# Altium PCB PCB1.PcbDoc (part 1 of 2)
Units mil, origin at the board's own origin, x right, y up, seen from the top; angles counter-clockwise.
Board outline 6184.85 x 2780 mil, 2 copper layers (Top Layer, Bottom Layer); 130 components, 145 nets, 531 pads, 99 vias.
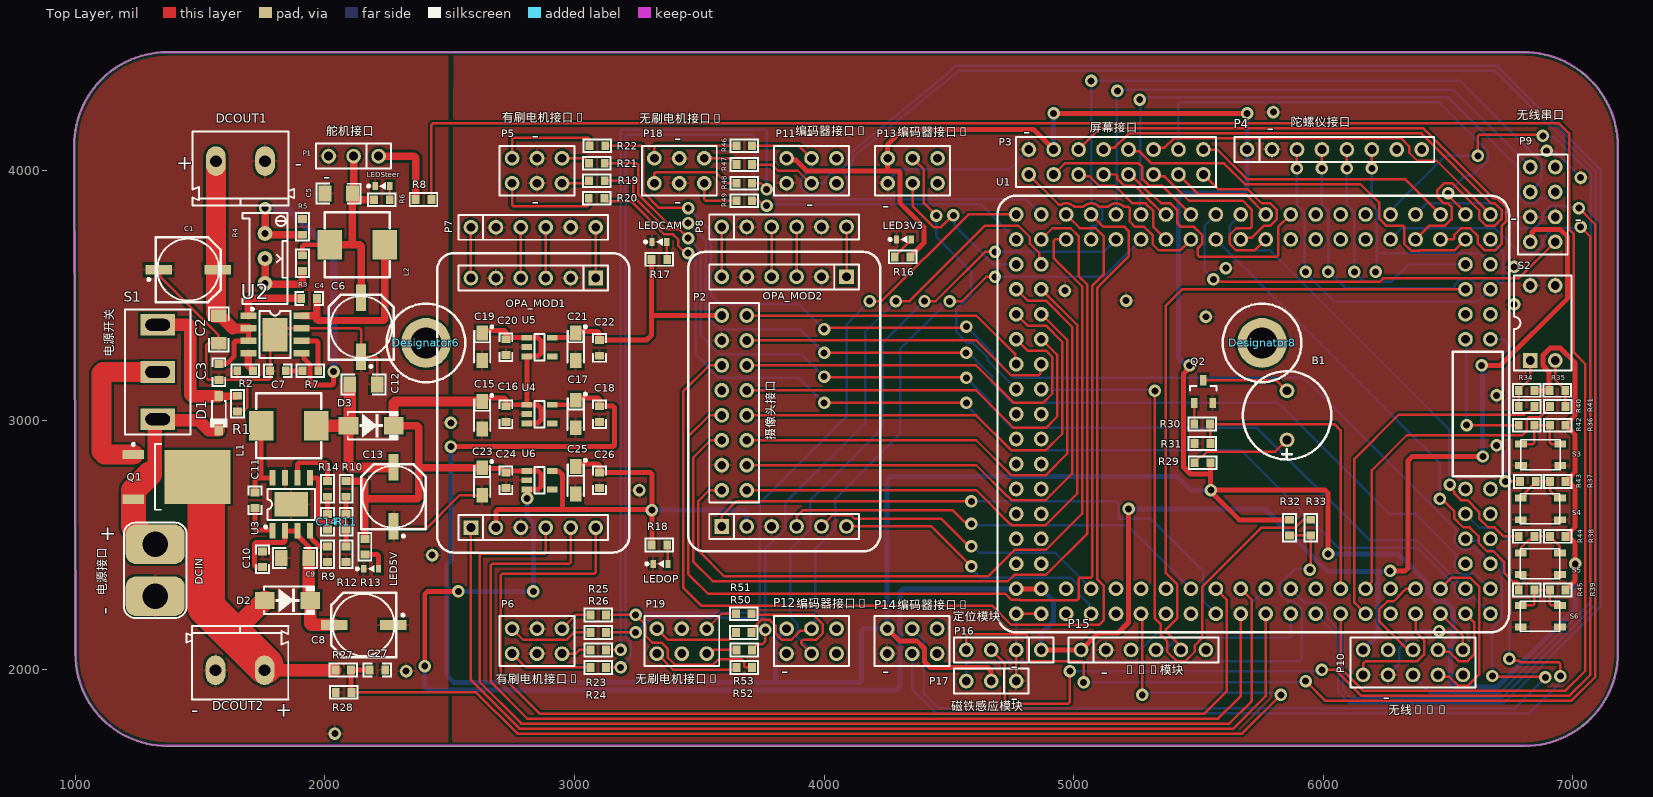
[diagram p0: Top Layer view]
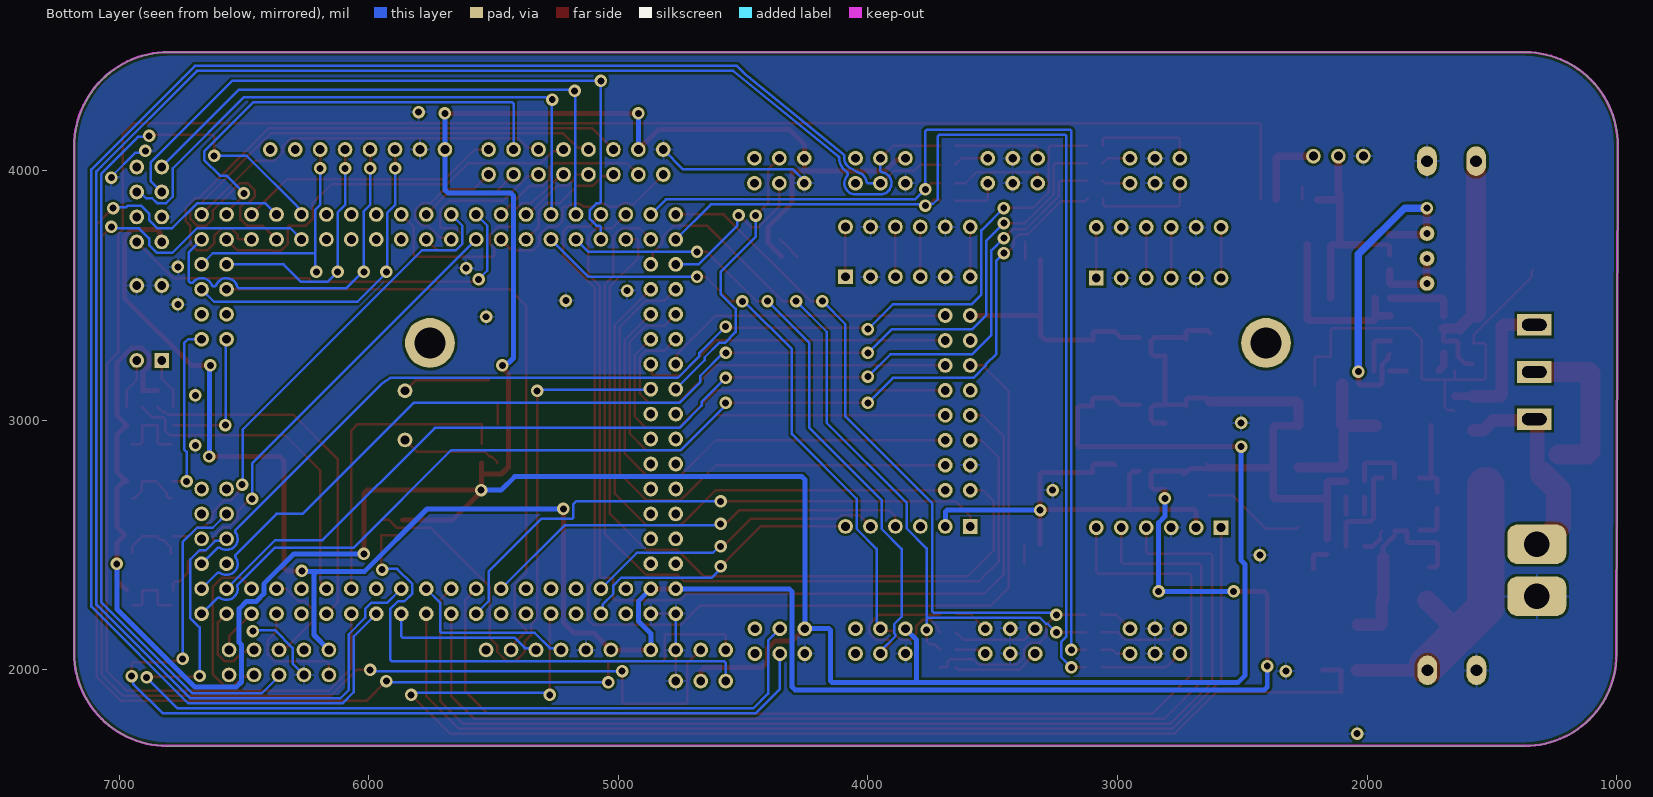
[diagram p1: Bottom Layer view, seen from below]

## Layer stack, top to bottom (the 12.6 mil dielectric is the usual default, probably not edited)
Top Solder: solder mask 0.4, Solder Resist, Dk 3.5
Top Layer: signal copper 1.4
Dielectric 1: dielectric 12.6, FR-4, Dk 4.8
Bottom Layer: signal copper 1.4
Bottom Solder: solder mask 0.4, Solder Resist, Dk 3.5

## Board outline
1000,2062.29 995.15,4100.04 cw(c1367.5,4102.54) 1364.99,4474.88 6802.71,4475 cw(c6802.71,4097.71) 7180,4097.71 7180,2067.32 cw(c6807.68,2067.32) 6807.68,1695 6810,1695 1370,1695 1367.29,1695 cw(c1367.29,2062.29)

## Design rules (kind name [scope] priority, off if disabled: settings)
Clearance [All] p1: gap=10 ignorepadtopadclearanceinfootprint=FALSE except(0: Arc-Hole Track-Hole SMDPad-Hole THPad-Hole Via-Hole Fill-Hole Poly-Hole Region-Hole Text-Hole)
PolygonConnect [All] p1: connectstyle=Relief reliefconductorwidth=10 reliefentries=4 polygonreliefangle="90 Angle" airgapwidth=10
RoutingVias [All] p1: holewidth=28 width=50 viastyle="Through Hole" minholewidth=28 minwidth=50 maxholewidth=28 maxwidth=50
SolderMaskExpansion [All] p1: expansion=4 istentingtop=FALSE
Width [InNetClass('New Class')] p1: maxlimit=20 minlimit=20 preferedwidth=20 minimp=50.000000 maximp=50.000000 favimp=50.000000
30 further rules are at their usual default settings.

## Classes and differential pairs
polygon class PolygonClass_1: GND_L01_P000

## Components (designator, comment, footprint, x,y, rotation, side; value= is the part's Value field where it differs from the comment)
B1 "BEEP" "BEEP 9x5.5mm" 5855,3020 r90 top
C1 "100uF 35V 铝电解" "CAP-E-S 6.3" 1451.89,3603.5 r180 top value=100uF
C2 "4.7uF 35V X5R" CAPC3216[1206]S 1575,3363.62 r90 top value=4.7uF
C3 "100nF 50V X7R" CAPC1608[0603]S-N 1575,3193.5 r90 top value=100nF
C4 "100nF 50V X7R" CAPC1608[0603]S-N 1936.5,3488.5 r0 top value=100nF
C5 "47uF 25V X5R" CAPC3216[1206]S 2054.88,3908.5 r180 top value=47uF
C6 "220uF 25V 铝电解" "CAP-E-S 6.3" 2145,3373.5 r270 top value=220uF
C7 "4.7nF 50V X7R" CAPC1608[0603]S-N 1811.5,3198.5 r0 top value=4.7nF
C8 "100uF 35V 铝电解" "CAP-E-S 6.3" 2155,2180 r0 top value=100uF
C9 "4.7uF 35V X5R" CAPC3216[1206]S 1880.12,2448.5 r0 top value=4.7uF
C10 "100nF 50V X7R" CAPC1608[0603]S-N 1750,2443.5 r90 top value=100nF
C11 "100nF 50V X7R" CAPC1608[0603]S-N 1720,2680 r90 top value=100nF
C12 "47uF 25V X5R" CAPC3216[1206]S 2155,3143.5 r180 top value=47uF
C13 "220uF 25V 铝电解" "CAP-E-S 6.3" 2275,2693.5 r270 top value=220uF
C14 "4.7nF 50V X7R" CAPC1608[0603]S-N 2010,2593.5 r90 top value=4.7nF
C15 "10uF 16V 钽电容" "CAP-T-S 3216" 2630,3020 r270 top value=10uF
C16 "100nF 50V X7R" CAPC1608[0603]S-N 2725,3025 r90 top value=100nF
C17 "10uF 16V 钽电容" "CAP-T-S 3216" 3005,3025 r270 top value=10uF
C18 "100nF 50V X7R" CAPC1608[0603]S-N 3100,3025 r90 top value=100nF
C19 "10uF 16V 钽电容" "CAP-T-S 3216" 2630,3294.88 r270 top value=10uF
C20 "100nF 50V X7R" CAPC1608[0603]S-N 2725,3293.5 r90 top value=100nF
C21 "10uF 16V 钽电容" "CAP-T-S 3216" 3005,3295 r270 top value=10uF
C22 "100nF 50V X7R" CAPC1608[0603]S-N 3100,3290 r90 top value=100nF
C23 "10uF 16V 钽电容" "CAP-T-S 3216" 2630,2755 r270 top value=10uF
C24 "100nF 50V X7R" CAPC1608[0603]S-N 2725,2760 r90 top value=100nF
C25 "10uF 16V 钽电容" "CAP-T-S 3216" 3005,2760 r270 top value=10uF
C26 "100nF 50V X7R" CAPC1608[0603]S-N 3100,2760 r90 top value=100nF
C27 "100nF 50V X7R" CAPC1608[0603]S-N 2210,2000 r0 top value=100nF
D1 "BZT52C16" SOD-123-L 1575,3028.5 r270 top
D2 "SS54" SMA-L[DO-214AC] 1850,2278.5 r0 top
D3 "SS54" SMA-L[DO-214AC] 2185,2978.5 r0 top
DCIN "T型插头" "Wired T-Header ThroughHole" 1320,2399.17 r0 top
DCOUT1 "KF/WJ/DG 30x connecter" "KF/WJ/DG 301-2p-5.0mm" 1661.57,4038.5 r180 top
DCOUT2 "KF/WJ/DG 30x connecter" "KF/WJ/DG 301-2p-5.0mm" 1660,1998.5 r0 top
Designator6 "Comment" M3x4_L 2405,3310 r0 top
Designator8 "Comment" M3x4_L 5755,3310 r0 top
L1 "4.7uH 5A" "0630 TPC 7*7*3" 1855,2978.5 r0 top value=4.7uH
L2 "4.7uH 5A" "0630 TPC 7*7*3" 2130,3703.5 r180 top value=4.7uH
LED3V3 "翠绿贴片LED" LEDC1608(0603)-L 4320,3725 r0 top
LED5V "翠绿贴片LED" LEDC1608(0603)-L 2185,2405 r0 top
LEDCAM "翠绿贴片LED" LEDC1608(0603)-L 3340,3715 r0 top
LEDOP "翠绿贴片LED" LEDC1608(0603)-L 3345,2425 r0 top
LEDSteer "翠绿贴片LED" LEDC1608(0603)-L 2230.47,3938.5 r0 top
OPA_MOD1 "OPA_MOD" SEEKFREE_4CHANEL_OPAMOD 2835,3070 r0 top
OPA_MOD2 "OPA_MOD" SEEKFREE_4CHANEL_OPAMOD 3840,3075 r0 top
P1 "Header-D-M 1x3P" HDR1X3-M 2215,4058.5 r180 top
P2 "Header-D-F 2x8P" HDR2X8-F 3690,2720 r90 top
P3 "Header-D-F 2x8P" HDR2X8-F 4820,3985 r0 top
P4 "Header-D-M 1x8P" HDR1X8-M 5695,4085 r0 top
P5 "Header-D-M 2x3P" HDR2X3-M 2950,4050 r180 top
P6 "Header-D-M 2x3P" HDR2X3-M 2950,2165 r180 top
P7 "Header-D-M 1x6P" HDR1X6-M 2585,3773.5 r0 top
P8 "Header-D-M 1x6P" HDR1X6-M 3590,3775 r0 top
P9 "Header-D-F 2x4P" HDR2X4-F 6830,4015 r270 top
P10 "Header-D-F 2x5P" HDR2X5-F 6560,2080 r180 top
P11 "Header-D-M 2x3P" HDR2X3-M 4050,4050 r180 top
P12 "Header-D-M 2x3P" HDR2X3-M 4050,2165 r180 top
P13 "Header-D-M 2x3P" HDR2X3-M 4455,4050 r180 top
P14 "Header-D-M 2x3P" HDR2X3-M 4453.03,2165 r180 top
P15 "Header-D-M 1x6P" HDR1X6-M 5030,2080 r0 top
P16 "Header-D-M 1x4P" HDR1X4-M 4870,2080 r180 top
P17 "Header-D-M 1x3P" HDR1X3-M 4770,1955 r180 top
P18 "Header-D-M 2x3P" HDR2X3-M 3320,3950 r0 top
P19 "Header-D-M 2x3P" HDR2X3-M 3330,2065 r0 top
Q1 "HY19P03" TO-252AA 1361.06,2773.5 r0 top
Q2 "S8050" SOT-23 5520,3115 r90 top
R1 "10K ±1%" RESC1608[0603]S-N 1650,3067.01 r90 top value=10K
R2 "200K ±1%" RESC1608[0603]S-N 1680,3198.5 r0 top value=200K
R3 "27K ±1%" RESC1608[0603]S-N 1910,3630 r90 top value=27K
R4 "50K" RESPOT3296W 1760,3648.5 r270 top
R5 "8.2K ±1%" RESC1608[0603]S-N 1910,3775 r90 top value=8.2K
R6 "10K ±1%" RESC1608[0603]S-N 2228.5,3883.5 r180 top value=10K
R7 "20K ±1%" RESC1608[0603]S-N 1941.5,3198.5 r0 top value=20K
R8 "100R ±1%" RESC1608[0603]S-N 2395,3885 r180 top value=100R
R9 "200K ±1%" RESC1608[0603]S-N 2010,2463.5 r90 top value=200K
R10 "51K ±1%" RESC1608[0603]S-N 2085,2725 r90 top value=51K
R11 "1.5K ±1%" RESC1608[0603]S-N 2085,2593.5 r90 top value=1.5K
R12 "10K ±1%" RESC1608[0603]S-N 2085,2463.5 r90 top value=10K
R13 "4.7K ±1%" RESC1608[0603]S-N 2160,2493.5 r90 top value=4.7K
R14 "20K ±1%" RESC1608[0603]S-N 2010,2725 r90 top value=20K
R16 "2.7K ±1%" RESC1608[0603]S-N 4315,3655 r180 top value=2.7K
R17 "2.7K ±1%" RESC1608[0603]S-N 3340,3645 r0 top value=2.7K
R18 "2.7K ±1%" RESC1608[0603]S-N 3340,2500 r0 top value=2.7K
R19 "100R ±1%" RESC1608[0603]S-N 3090,3960 r180 top value=100R
R20 "100R ±1%" RESC1608[0603]S-N 3088.5,3890 r0 top value=100R
R21 "100R ±1%" RESC1608[0603]S-N 3090,4030 r180 top value=100R
R22 "100R ±1%" RESC1608[0603]S-N 3091.5,4100 r0 top value=100R
R23 "100R ±1%" RESC1608[0603]S-N 3095,2080 r180 top value=100R
R24 "100R ±1%" RESC1608[0603]S-N 3095,2010 r0 top value=100R
R25 "100R ±1%" RESC1608[0603]S-N 3095,2220 r180 top value=100R
R26 "100R ±1%" RESC1608[0603]S-N 3095,2150 r0 top value=100R
R27 "200K ±1%" RESC1608[0603]S-N 2073.5,2000 r0 top value=200K
R28 "20K ±1%" RESC1608[0603]S-N 2075,1910 r180 top value=20K
R29 "10R ±1%" RESC1608[0603]S-N 5516.5,2830 r180 top value=10R
R30 "4.7K ±1%" RESC1608[0603]S-N 5515,2985 r180 top value=4.7K
R31 "1K ±1%" RESC1608[0603]S-N 5516.34,2906.81 r180 top value=1K
R32 "10K ±1%" RESC1608[0603]S-N 5865,2570 r90 top value=10K
R33 "100R ±1%" RESC1608[0603]S-N 5950,2570 r270 top value=100R
R34 "4.7K ±1%" RESC1608[0603]S-N 6815,3120 r180 top value=4.7K
R35 "4.7K ±1%" RESC1608[0603]S-N 6938.5,3120 r0 top value=4.7K
R36 "4.7K ±1%" RESC1608[0603]S-N 6940,2980 r180 top value=4.7K
R37 "4.7K ±1%" RESC1608[0603]S-N 6940,2755 r180 top value=4.7K
R38 "4.7K ±1%" RESC1608[0603]S-N 6940,2535 r180 top value=4.7K
R39 "4.7K ±1%" RESC1608[0603]S-N 6940,2320 r180 top value=4.7K
R40 "470R ±1%" RESC1608[0603]S-N 6815,3055 r0 top value=470R
R41 "470R ±1%" RESC1608[0603]S-N 6940,3055 r180 top value=470R
R42 "470R ±1%" RESC1608[0603]S-N 6815,2980 r180 top value=470R
R43 "470R ±1%" RESC1608[0603]S-N 6820,2755 r180 top value=470R
R44 "470R ±1%" RESC1608[0603]S-N 6815,2535 r180 top value=470R
R45 "470R ±1%" RESC1608[0603]S-N 6815,2320 r180 top value=470R
R46 "100R ±1%" RESC1608[0603]S-N 3680,4100 r180 top value=100R
R47 "100R ±1%" RESC1608[0603]S-N 3680,4025 r0 top value=100R
R48 "100R ±1%" RESC1608[0603]S-N 3680,3950 r180 top value=100R
R49 "100R ±1%" RESC1608[0603]S-N 3680,3880 r0 top value=100R
R50 "100R ±1%" RESC1608[0603]S-N 3678.5,2150 r180 top value=100R
R51 "100R ±1%" RESC1608[0603]S-N 3678.5,2225 r0 top value=100R
R52 "100R ±1%" RESC1608[0603]S-N 3680,2010 r180 top value=100R
R53 "100R ±1%" RESC1608[0603]S-N 3680,2080 r0 top value=100R
S1 "SW-SPDT" SS12D10 1330,3193.5 r90 top
S2 "SW DIP-2" "Code SW-2-DIP-2.54" 6880,3390 r0 top
S3 "Button" PTS810-3*4-CurvePin 6871.26,2861.69 r0 top
S4 "Button" PTS810-3*4-CurvePin 6870,2645 r0 top
S5 "Button" PTS810-3*4-CurvePin 6870,2425 r0 top
S6 "Button" PTS810-3*4-CurvePin 6870,2215 r0 top
U1 "TC264_CoreBoard" TC264_CoreBoard 4770,2225 r90 top
U2 "SP1N28STER" SOP-8E 1800,3343.5 r0 top
U3 "SP1N28STER" SOP-8E 1865,2663.5 r90 top
U4 "RT9013-33" SOT-23-5 2860,3025 r0 top
U5 "RT9013-33" SOT-23-5 2860,3293.5 r0 top
U6 "RT9013-33" SOT-23-5 2860,2760 r0 top

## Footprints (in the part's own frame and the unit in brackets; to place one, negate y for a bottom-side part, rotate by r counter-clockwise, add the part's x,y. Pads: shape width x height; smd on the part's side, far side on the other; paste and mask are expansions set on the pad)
"0630 TPC 7*7*3" [mm] "12mmx12mmx6.5mm 一体成型功率电感"
  rect 2.5x3 smd: 1(-2.8,0) 2(2.8,0)
  silkscreen extent -3.3,-3.3 3.3,3.3, body extent -3.3,-3.3 3.3,3.3, height 3
"BEEP 9x5.5mm" [mm] "蜂鸣器 9x5.5mm"
  round 1.5 hole 0.9: 1(-2.5,0) 2(2.5,0)
  silkscreen extent -4.5,-4.5 4.5,4.5, body extent -4.8,-4.8 4.8,4.8, height 5.05
"CAP-E-S 6.3" [mm] "贴片 铝电解电容 6.3mm"
  rect 2.7x1 smd: 1(-3,0) 2(3,0)
  silkscreen extent -3.3,-3.3 4.12,3.3, body extent -3.5,-3.3 3.5,3.3, height 5.2
"CAP-T-S 3216" [mm] "贴片 钽电容 A型 3216"
  rect 1.5x1.2 smd: 1(-1.4,0) 2(1.4,0)
  silkscreen extent -2.15,-0.9 1.6,1.1, body extent -1.6,-0.8 1.6,0.8, height 1.6
CAPC1608[0603]S-N [mm] "0603贴片电容 有丝印 2脚 1.60x0.80mm IPC中密度"
  rect 0.8x0.9 smd: 1(-0.8,0) 2(0.8,0)
  silkscreen extent -1.5,-0.75 1.5,0.75, body extent -0.8,-0.41 0.8,0.41, height 0.79
CAPC3216[1206]S [mm] "1206贴片电容 有丝印 2脚 3.20x1.60mm IPC中密度"
  rect 1.3x1.6 smd: 1(-1.4,0) 2(1.4,0)
  silkscreen extent -2.35,-1.11 2.35,1.11, body extent -1.6,-0.81 1.6,0.81, height 1.21
"Code SW-2-DIP-2.54" [mm] "2位直插拨码开关 间距2.54"
  rect 1.5x1.5 hole 0.9: 1(-1.27,-3.81)
  round 1.5 hole 0.9: 2(1.27,-3.81) 3(1.27,3.81) 4(-1.27,3.81)
  silkscreen extent -2.93,-4.85 2.93,4.85, body extent -3.04,-4.95 3.04,4.95, height 7.03
HDR1X3-M [mm] "1x3pin, 2.54mm间距, 直插, 直排针"
  round 1.5 hole 0.9: 1(0,0) 2(2.54,0) 3(5.08,0)
  silkscreen extent -1.27,-1.27 6.35,1.27, body extent -1.27,-1.27 6.35,1.27, height 8.54
HDR1X4-M [mm] "1x4pin, 2.54mm间距, 直插, 直排针"
  round 1.5 hole 0.9: 1(0,0) 2(2.54,0) 3(5.08,0) 4(7.62,0)
  silkscreen extent -1.27,-1.27 8.89,1.27, body extent -1.27,-1.27 8.89,1.27, height 8.54
HDR1X6-M [mm] "1x6pin, 直插, 直排针, 2.54mm间距"
  round 1.5 hole 0.9: 1(0,0) 2(2.54,0) 3(5.08,0) 4(7.62,0) 5(10.16,0) 6(12.7,0)
  silkscreen extent -1.27,-1.27 13.97,1.27, body extent -1.27,-1.27 13.97,1.27, height 8.54
HDR1X8-M [mm] "1x7pin, 2.54mm间距, 直插, 直排针"
  round 1.5 hole 0.9: 1(0,0) 2(2.54,0) 3(5.08,0) 4(7.62,0) 5(10.16,0) 6(12.7,0) 7(15.24,0) 8(17.78,0)
  silkscreen extent -1.27,-1.27 19.05,1.27, body extent -1.27,-1.27 19.05,1.27, height 8.54
HDR2X3-M [mm] "2x3pin, 2.54mm间距, 直插, 直排针"
  round 1.5 hole 0.9: 1(0,0) 2(0,2.54) 3(2.54,0) 4(2.54,2.54) 5(5.08,0) 6(5.08,2.54)
  silkscreen extent -1.27,-1.27 6.35,3.81, body extent -1.27,-1.27 6.35,3.81, height 8.54
HDR2X4-F [mm] "2x4pin, 2.54mm间距, 直插, 直排座"
  round 1.5 hole 0.9: 1(0,0) 2(0,2.54) 3(2.54,0) 4(2.54,2.54) 5(5.08,0) 6(5.08,2.54) 7(7.62,0) 8(7.62,2.54)
  silkscreen extent -1.27,-1.27 8.89,3.81, body extent -1.5,-1.26 9.16,3.82, height 8.5
HDR2X5-F [mm] "2x5pin, 2.54mm间距, 直插, 直排座"
  round 1.5 hole 0.9: 1(0,0) 2(0,2.54) 3(2.54,0) 4(2.54,2.54) 5(5.08,0) 6(5.08,2.54) 7(7.62,0) 8(7.62,2.54) 9(10.16,0) 10(10.16,2.54)
  silkscreen extent -1.27,-1.27 11.43,3.81, body extent -1.52,-1.26 11.68,3.82, height 8.5
HDR2X8-F [mm] "2x8pin, 2.54mm间距, 直插, 直排座"
  round 1.5 hole 0.9: 1(0,0) 2(0,2.54) 3(2.54,0) 4(2.54,2.54) 5(5.08,0) 6(5.08,2.54) 7(7.62,0) 8(7.62,2.54) 9(10.16,0) 10(10.16,2.54) 11(12.7,0) 12(12.7,2.54) 13(15.24,0) 14(15.24,2.54) 15(17.78,0) 16(17.78,2.54)
  silkscreen extent -1.27,-1.27 19.05,3.81, body extent -1.52,-1.27 19.3,3.81, height 8.5
"KF/WJ/DG 301-2p-5.0mm" [mm] "2P 5mm间距 接线端子"
  oval 2x3 hole 1.2: 1(2.5,0) 2(-2.5,0)
  silkscreen extent -5.47,-3 4.9,4.5, body extent -5.6,-3 5,4.6, height 10.1
LEDC1608(0603)-L [mm] "LED,Chip;1.60mm L X 0.80mm W X 0.80mm H"
  rect 0.55x0.8 smd: A(0.75,0) C(-0.75,0)
  silkscreen extent -1.52,-0.38 0.33,0.38, body extent -0.8,-0.4 0.8,0.4, height 0.64
M3x4_L [mil] "M3铜柱，长：4mm"
  round 200 hole 125: 1(0,0)
  silkscreen extent -157,-157 157,157, body extent -106,-93 106,93, height 159
PTS810-3*4-CurvePin [mm] "3*4 白色 汽车遥控器贴片按键 包脚"
  rect 1.2x0.7 smd: 1(-2,-1.1) 1(2,-1.1) 2(-2,1.1) 2(2,1.1)
  silkscreen extent -2.02,-1.52 2,1.52, body extent -2.3,-1.6 2.3,1.6, height 2.5
RESC1608[0603]S-N [mm] "0603贴片电阻 有丝印 2脚 1.60x0.80mm IPC中密度"
  rect 0.8x0.9 smd: 1(-0.8,0) 2(0.8,0)
  silkscreen extent -1.5,-0.75 1.5,0.75, body extent -0.8,-0.4 0.8,0.4, height 0.45
RESPOT3296W [mm] "3296W 精密可调电阻 顶调"
  round 1.5 hole 0.7: 1(-2.54,0) 2(2.54,0) ADJ(0,0)
  silkscreen extent -4.65,-2.3 4.65,2.3, body extent -4.75,-2.4 4.75,2.4, height 3.1
SEEKFREE_4CHANEL_OPAMOD [mm]
  rect 1.5x1.5 hole 0.9: 1(6.35,12.7) 7(-6.35,-12.7)
  round 1.5 hole 0.9: 2(3.81,12.7) 3(1.27,12.7) 4(-1.27,12.7) 5(-3.81,12.7) 6(-6.35,12.7) 8(-3.81,-12.7) 9(-1.27,-12.7) 10(1.27,-12.7) 11(3.81,-12.7) 12(6.35,-12.7)
  Top Overlay keep-out lines w0.254: -9.779,-13.524 ccw(c-8.063,-13.524) -8.063,-15.24 8.063,-15.24 ccw(c8.063,-13.524) 9.779,-13.524 9.779,13.524 ccw(c8.063,13.524) 8.063,15.24 -8.063,15.24 ccw(c-8.063,13.524) -9.779,13.524 -9.779,-13.524
  silkscreen extent -9.78,-15.24 9.78,15.24, body extent -7.75,-13.98 7.75,13.98, height 8.54
SMA-L[DO-214AC] [mm] "SMA 二极管 贴片 IPC高密度"
  rect 2x1.75 smd: A(-2.3,0) K(2.3,0)
  silkscreen extent -2.37,-1.4 2.7,1.4, body extent -2.9,-1.46 2.91,1.46, height 2.3
SOD-123-L [mm] "SOD Diode;2.70mm W X 1.60mm L X 1.35mm H body"
  rect 1x0.85 smd: A(-1.75,0) K(1.75,0)
  silkscreen extent -1.32,-0.9 1.47,0.9, body extent -1.85,-0.8 1.85,0.8, height 1.2
SOP-8E [mm] "SOIC,1.27mm pitch;8 pin,3.90mm W X 4.88mm L X 1.73mm H body"
  rect 2.5x3.4 smd: 0(0,0)
  rect 1.6x0.65 smd: 1(-2.7,1.905) 2(-2.7,0.635) 3(-2.7,-0.635) 4(-2.7,-1.905) 5(2.7,-1.905) 6(2.7,-0.635) 7(2.7,0.635) 8(2.7,1.905)
  silkscreen extent -2.42,-2.4 1.58,2.72, body extent -3.11,-2.45 3.11,2.45, height 1.75
SOT-23 [mm] "SOT23, 3-Leads, Body 2.90x2.40mm, Pitch 0.95mm, IPC Medium Density"
  rect 1.05x0.65 smd: 1(-1.15,0.95) 2(-1.15,-0.95) 3(1.15,0)
  silkscreen extent 0.13,-1.35 0.58,1.35, body extent -1.4,-1.45 1.4,1.45, height 1.2
SOT-23-5 [mm] "SOT23, 5-Leads, Body 2.92x2.79mm, Pitch 0.95mm, IPC Medium Density"
  rect 1.1x0.6 smd: 1(-1.3,0.95) 2(-1.3,0) 3(-1.3,-0.95) 4(1.3,-0.95) 5(1.3,0.95)
  silkscreen extent -0.53,-1.35 0.53,1.35, body extent -1.42,-1.46 1.42,1.46, height 1.08
SS12D10 [mm] "拨动开关，直脚，脚距4.8"
  rect 2.2x3.5 hole 1.2 slot 2.5 at 90 deg mask+0.07: 1(-4.8,0) 2(0,0) 3(4.8,0)
  silkscreen extent -6.35,-3.35 6.35,3.35, body extent -6.4,-3.3 6.35,3.8, height 12.5
TC264_CoreBoard [mm] "逐飞科技TC264核心板"
  round 1.5 hole 0.9: 1(0,0) 2(2.54,0) 3(0,-2.54) 4(2.54,-2.54) 5(0,-5.08) 6(2.54,-5.08) 7(0,-7.62) 8(2.54,-7.62) 9(0,-10.16) 10(2.54,-10.16) 11(0,-12.7) 12(2.54,-12.7) 13(0,-15.24) 14(2.54,-15.24) 15(0,-17.78) 16(2.54,-17.78) 17(0,-20.32) 18(2.54,-20.32) 19(0,-22.86) 20(2.54,-22.86) 21(0,-25.4) 22(2.54,-25.4) 23(0,-27.94) 24(2.54,-27.94) 25(0,-30.48) 26(2.54,-30.48) 27(0,-33.02) 28(2.54,-33.02) 29(0,-35.56) 30(2.54,-35.56) 31(0,-38.1) 32(2.54,-38.1) 33(0,-40.64) 34(2.54,-40.64) 35(0,-43.18) 36(2.54,-43.18) 37(0,-45.72) 38(2.54,-45.72) 39(0,-48.26) 40(2.54,-48.26) 41(5.08,-48.26) 42(5.08,-45.72) 43(7.62,-48.26) 44(7.62,-45.72) 45(10.16,-48.26) 46(10.16,-45.72) 47(12.7,-48.26) 48(12.7,-45.72) 49(27.94,-45.72) 50(27.94,-48.26) 51(30.48,-45.72) 52(30.48,-48.26) 53(33.02,-45.72) 54(33.02,-48.26) 55(35.56,-45.72) 56(35.56,-48.26) 57(38.1,-48.26) 58(40.64,-48.26) 59(38.1,-45.72) 60(40.64,-45.72) 61(38.1,-43.18) 62(40.64,-43.18) 63(38.1,-40.64) 64(40.64,-40.64) 65(38.1,-38.1) 66(40.64,-38.1) 67(38.1,-35.56) 68(40.64,-35.56) 69(38.1,-33.02) 70(40.64,-33.02) 71(38.1,-30.48) 72(40.64,-30.48) 73(38.1,-27.94) 74(40.64,-27.94) 75(38.1,-25.4) 76(40.64,-25.4) 77(38.1,-22.86) 78(40.64,-22.86) 79(38.1,-20.32) 80(40.64,-20.32) 81(38.1,-17.78) 82(40.64,-17.78) 83(38.1,-15.24) 84(40.64,-15.24) 85(38.1,-12.7) 86(40.64,-12.7) 87(38.1,-10.16) 88(40.64,-10.16) 89(38.1,-7.62) 90(40.64,-7.62) 91(38.1,-5.08) 92(40.64,-5.08) 93(38.1,-2.54) 94(40.64,-2.54) 95(38.1,0) 96(40.64,0) 97(35.56,-2.54) 98(35.56,0) 99(33.02,-2.54) 100(33.02,0) 101(30.48,-2.54) 102(30.48,0) 103(27.94,-2.54) 104(27.94,0) 105(25.4,-2.54) 106(25.4,0) 107(22.86,-2.54) 108(22.86,0) 109(20.32,-2.54) 110(20.32,0) 111(17.78,-2.54) 112(17.78,0) 113(15.24,-2.54) 114(15.24,0) 115(12.7,-2.54) 116(12.7,0) 117(10.16,-2.54) 118(10.16,0) 119(7.62,-2.54) 120(7.62,0) 121(5.08,-2.54) 122(5.08,0)
  silkscreen extent -1.91,-50.16 42.55,1.91
TO-252AA [mm] "D-PAK, 4-Leads, Body 6.1x6.5mm, Pitch 2.28mm, Lead Span 9.8mm, IPC Low Density"
  rect 6.7x5.5 smd: 1(3.275,0)
  rect 2.2x0.95 smd: 2(-3.275,2.28) 3(-3.275,-2.28)
  silkscreen extent -3.4,-3.35 -0.47,3.43, body extent -3.77,-3.27 6.16,3.27, height 2.39
"Wired T-Header ThroughHole" [mm] "带线T头直插焊盘"
  rrect50% 6x4 hole 2.6: 1(0,2.65) 2(0,-2.65)
  silkscreen extent -3.2,-4.85 3.2,4.85

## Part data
B1: "蜂鸣器"
C1 C8: library part "E-S 100uF 35V 6.3x7.7", "贴片电解电容 100uF 35V 6.3x7.7", Voltage=35V
C2 C9: library part "4.7uF 1206 35V X5R", "贴片瓷片电容; MLCC; 1206(3216);", Voltage=35V
C3 C4 C10 C11 C16 C18 C20 C22 C24 C26 C27: library part "100nF 0603 50V X7R", "贴片瓷片电容; MLCC; 0603(1608);", Voltage=50V
C5 C12: library part "47uF 1206 25V X5R", "贴片瓷片电容; MLCC; 1206(3216);", Voltage=25V
C6 C13: library part "E-S 220uF 25V 6.3x7.7", "贴片电解电容 220uF 25V 6.3x7.7", Voltage=25V
C7 C14: library part "4.7nF 0603 50V X7R", "贴片瓷片电容; MLCC; 0603(1608);", Voltage=50V
C15 C17 C19 C21 C23 C25: library part "T-S 10uF 3216 16V", "贴片钽电容 10uF 3216 16V", Voltage=16V
D1: library part "Diode Zen", "稳压二极管 齐纳二极管  Zener Diode"
D2 D3: "SS54 肖特基二极管"
DCIN: library part T_Header
DCOUT1 DCOUT2: library part "KF/WJ/DG 30x", "接线端子 2Pin"
L1 L2: library part Ind-Power, "功率电感"
LED3V3 LED5V LEDCAM LEDOP LEDSteer: library part "LED Chip Green"
OPA_MOD1 OPA_MOD2: library part OPA_4CHANNEL_SEEKFREE, "逐飞科技 运放模块"
P1 P17: "1x3pin, 直插, 排针"
P2 P3: "2x8pin, 直插, 双排座"
P4: "1x8pin, 直插, 排针"
P5 P6 P11 P12 P13 P14 P18 P19: "2x3pin, 直插, 双排针"
P7 P8 P15: "1x6pin, 直插, 排针"
P9: "2x4pin, 直插, 双排座"
P10: "2x5pin, 直插, 双排座"
P16: "1x4pin, 直插, 排针"
Q1: "HY19P03 P-Channel MOSFET"
Q2: library part "NPN S8050", "NPN 三极管"
R1 R6 R12 R32: library part Res-Chip, "贴片电阻", Power=1/8W, Tolerance=±1%
R2 R9 R27: library part Res-Chip_1, "贴片电阻", Power=1/8W, Tolerance=±1%
R3: library part Res-Chip_7, "贴片电阻", Power=1/8W, Tolerance=±1%
R4: library part Res-Adj-3p, "可调电阻"
R5: library part Res-Chip_8, "贴片电阻", Power=1/8W, Tolerance=±1%
R7 R14 R28: library part Res-Chip_4, "贴片电阻", Power=1/8W, Tolerance=±1%
R8 R19 R20 R21 R22 R23 R24 R25 R26 R33 R46 R47 R48 R49 R50 R51 R52 R53: library part Res-Chip_9, "贴片电阻", Power=1/8W, Tolerance=±1%
R10: library part Res-Chip_2, "贴片电阻", Power=1/8W, Tolerance=±1%
R11: library part Res-Chip_5, "贴片电阻", Power=1/8W, Tolerance=±1%
R13 R30 R34 R35 R36 R37 R38 R39: library part Res-Chip_3, "贴片电阻", Power=1/8W, Tolerance=±1%
R16 R17 R18: library part Res-Chip_6, "贴片电阻", Power=1/8W, Tolerance=±1%
R29: library part Res-Chip_10, "贴片电阻", Power=1/8W, Tolerance=±1%
R31: library part Res-Chip_11, "贴片电阻", Power=1/8W, Tolerance=±1%
R40 R41 R42 R43 R44 R45: library part Res-Chip_12, "贴片电阻", Power=1/8W, Tolerance=±1%
S1: "单刀双掷开关 3脚船型、钮子、拨动开关 SPDT Subminiature Toggle Switch"
S2: library part "Code SW-2", "2位拨码开关"
S3 S4 S5 S6: library part KEY, "按键"
U1: "逐飞科技TC264核心板"
U4 U5 U6: "3.3V 500mA SOT-23-5 LDO"

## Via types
v1: diameter 50, hole 28, Top Layer to Bottom Layer, 99 vias

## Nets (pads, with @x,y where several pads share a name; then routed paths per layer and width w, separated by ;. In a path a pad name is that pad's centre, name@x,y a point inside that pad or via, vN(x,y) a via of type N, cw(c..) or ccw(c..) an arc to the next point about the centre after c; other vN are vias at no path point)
00.0: P2.1 U1.99 | length 2313.7
  Top Layer w10: P2.1@3690,2720 4610,2720 4747.42,2582.58 4749.44,2582.58 4751.56,2580.47 4888.44,2580.47 5014.53,2706.56 5014.53,3381.96 4871.48,3525 U1.99@4870,3525
00.1: P2.3 U1.100 | length 2280.6
  Top Layer w10: P2.3@3690,2820 4610,2820 4735,2695 4737.03,2695 4751.56,2680.47 4888.44,2680.47 4994.53,2786.56 4994.53,3373.67 4888.67,3479.53 4815.47,3479.53 U1.100@4770,3525
00.2: P2.5 U1.101 | length 1980.7
  Top Layer w10: P2.5@3690,2920 4610,2920 4749.53,2780.47 4888.67,2780.47 4974.53,2866.33 4974.53,3321.96 4871.48,3425 U1.101@4870,3425
00.3: P2.7 U1.102 | length 1947.6
  Top Layer w10: P2.7@3690,3020 4610,3020 4749.53,2880.47 4888.67,2880.47 4954.53,2946.33 4954.53,3313.67 4888.67,3379.53 4815.47,3379.53 U1.102@4770,3425
00.4: P2.9 U1.103 | length 1662.4
  Top Layer w10: P2.9@3690,3120 4610,3120 4760,2970 4888.67,2970 4934.53,3015.86 4934.53,3261.96 4871.48,3325 U1.103@4870,3325
00.5: P2.11 U1.104 | length 1623.4
  Top Layer w10: P2.11@3690,3220 4610,3220 4760.47,3069.53 4877.5,3069.53 4914.53,3106.56 4914.53,3253.67 4888.67,3279.53 4815.47,3279.53 U1.104@4770,3325
00.6: P2.13 U1.105 | length 1276.4
  Top Layer w10: P2.13@3690,3320 4610,3320 4749.53,3180.47 4859.84,3180.47 4865.7,3186.33 4865.7,3220.7 U1.105@4870,3225
00.7: P2.15 U1.106 | length 1181.3
  Top Layer w10: P2.15@3690,3420 4610,3420 4766.33,3263.67 4766.33,3228.67 U1.106@4770,3225
00.8: R33.1 U1.107 | length 2484.9
  Top Layer w10: v1(5325.47,3118.34) 5325.47,2206.56 5350,2182.03 5350,2139.53 5374.53,2115 5374.53,2072.5 5411.56,2035.47 5448.44,2035.47 5485.47,2072.5 5485.47,2098.44 5514.53,2127.5 5514.53,2332.5 5751.28,2569.25 5887.43,2569.25 5903.11,2584.92 5919.68,2601.5 R33.1@5950,2601.5
  Bottom Layer w10: U1.107@4870,3125 4873.33,3121.67 5322.14,3121.67 v1(5325.47,3118.34)
00.9: P13.3 U1.108 | length 1160.2
  Top Layer w10: P13.3@4355,4050 4400,4005 4400,3870 v1(4450,3820)
  Bottom Layer w10: v1(4450,3820) 4450,3735 4590,3595 4590,3506.86 4530,3446.86 4530,3353.43 4573.43,3310 4596.57,3310 4653.76,3252.81 4653.76,3241.24 U1.108@4770,3125
02.0: P2.12 U1.90 | length 4538.5
  Top Layer w10: P2.12@3590,3220 3540,3220 3435,3115 3435,2330 3507.28,2257.72 4672.28,2257.72 4750,2180 5101.72,2180 5120,2198.28 5120,2337.97 5095,2362.97 5095,3531.72 5220,3656.72 5220,3759.27 5204.27,3775 5120,3775 U1.90@5070,3825
02.1: P2.2 U1.91 | length 3188.3
  Top Layer w10: P2.2@3590,2720 3540,2720 3495,2675 3495,2480 3600,2375 4657.03,2375 4762.5,2480.47 4888.44,2480.47 5034.53,2626.56 5034.53,3535.47 4920,3650 4920,3719.14 4925.86,3725 U1.91@4970,3725
02.2: P2.8 U1.92 | length 4036.1
  Top Layer w10: P2.8@3590,3020 3540,3020 3455,2935 3455,2385 3535,2305 4727.03,2305 4751.56,2280.47 4784.53,2280.47 4785,2280 5014.14,2280 5020,2285.86 5020,2363.67 5025.86,2369.53 5069.14,2369.53 5075,2375.39 5075,3540 5120,3585 5120,3737.97 5088.44,3769.53 5025.47,3769.53 U1.92@4970,3825
02.3: P2.6 U1.93 | length 3638.6
  Top Layer w10: P2.6@3590,2920 3545,2920 3475,2850 3475,2435 3555,2355 4737.03,2355 4762.5,2380.47 4888.44,2380.47 5055,2547.03 5055,3543.28 5020,3578.28 5020,3737.97 4988.44,3769.53 4914.53,3769.53 U1.93@4870,3725
02.4: R23.1 R48.1 U1.94 | length 4172.9
  Top Layer w10: R23.1@3126.5,2080 v1(3185,2080) ; R48.1@3711.5,3950 3746.72,3950 3770,3926.72 v1(3770,3925)
  Bottom Layer w10: v1(3185,2080) 3185,4159.14 3190.86,4165 3764.14,4165 3770,4159.14 v1(3770,3925) 3771.57,3925 3811.1,3885.47 4809.53,3885.47 U1.94@4870,3825
02.5: R24.2 R49.2 U1.95 | length 4176.6
  Top Layer w10: R24.2@3126.5,2010 v1(3185,2010) ; R49.2@3711.5,3880 3715.11,3883.61 3736.39,3883.61 3760,3860 v1(3770,3860)
  Bottom Layer w10: v1(3185,2010) 3225,2050 3225,2113.43 3205,2133.43 3205,4139.14 3210.86,4145 3714.14,4145 3720,4139.14 3720,3885.86 3738.2,3867.65 3762.35,3867.65 v1(3770,3860) 3775.47,3865.47 4629.53,3865.47 U1.95@4770,3725
02.6: R25.1 R52.1 U1.96 | length 3407
  Top Layer w10: R25.1@3126.5,2220 v1(3245,2220) 3285.47,2179.53 3285.47,2135.61 3311.56,2109.53 3348.44,2109.53 3374.53,2083.44 3374.53,2048.76 3402.81,2020.47 3555.47,2020.47 3577.72,2042.72 3670.47,2042.72 3679.25,2033.93 3679.25,2015.86 3685.11,2010 R52.1@3711.5,2010 ; v1(4182.5,3477.5) 4230.93,3477.5 4578.43,3825 U1.96@4770,3825
  Bottom Layer w10: v1(3245,2220) 3252.65,2227.65 3268.98,2227.65 3270.86,2229.53 3737.18,2229.53 3743.04,2235.39 3743.04,2668.04 4090,3015 4090,3385 v1(4182.5,3477.5)
02.7: R26.2 R53.2 U1.97 | length 3133.4
  Top Layer w10: R26.2@3126.5,2150 v1(3245,2150) ; R53.2@3711.5,2080 3711.5,2081.97 3731.87,2102.35 3752.35,2102.35 3765,2115 v1(3765,2160) ; v1(4287.5,3477.5) 4342.5,3477.5 4645,3780 4777.97,3780 4824.53,3733.44 4824.53,3707.5 4862.5,3669.53 4862.5,3632.5 U1.97@4870,3625 U1.97@4856.73,3625
  Bottom Layer w10: v1(3245,2150) 3280,2185 3287.03,2185 3311.56,2209.53 3765,2209.53 ; v1(3765,2160) 3765,2209.53 ; v1(4287.5,3477.5) 4165,3355 4165,2990 3845.47,2670.47 3845.47,2567.5 3765,2487.03 3765,2209.53
02.8: P13.4 U1.98 | length 664
  Top Layer w10: P13.4@4355,3950 4355,3858.43 4439.29,3774.14 4468.52,3774.14 4515.95,3821.57 v1(4518.43,3821.57)
  Bottom Layer w10: v1(4518.43,3821.57) 4523.43,3816.57 4523.43,3780 4678.43,3625 U1.98@4770,3625
10.1: P12.3 R50.1 U1.85 | length 2750.5
  Top Layer w10: R50.1@3710,2150 3720.75,2160.75 3720.75,2172.32 3748.43,2200 3781.57,2200 3805.47,2176.1 3805.47,2146.56 3831.56,2120.47 3868.44,2120.47 3905.47,2157.5 3942.5,2157.5 P12.3@3950,2165 ; v1(4503.28,3476.72) 4551.72,3476.72 4650,3575 v1(4685,3575)
  Bottom Layer w10: P12.3@3950,2165 3950,2178.27 3965,2193.27 3965,2485 4045,2565 4045,2685 4305,2945 4305,3285 4496.72,3476.72 v1(4503.28,3476.72) ; v1(4685,3575) 5120,3575 U1.85@5270,3725
10.2: P9.4 U1.86 | length 2391.7
  Bottom Layer w10: U1.86@5270,3825 5267.5,3827.5 5267.5,4282.5 v1(5265,4285) 5272.65,4292.65 5288.51,4292.65 5290.86,4295 6500,4295 6785.47,4009.53 6785.47,3896.56 6811.56,3870.47 6848.44,3870.47 6867.97,3890 6892.03,3890 6917.03,3915 P9.4@6930,3915
10.3: P12.4 R51.2 U1.87 | length 3048
  Top Layer w10: R51.2@3710,2225 3715,2220 3957.97,2220 3994.53,2183.44 3994.53,2146.56 3968.44,2120.47 3914.53,2120.47 3908.67,2114.61 3908.67,2106.33 P12.4@3950,2065 ; v1(4402.5,3477.5) 4447.5,3477.5 4645,3675 v1(4685,3675)
  Bottom Layer w10: P12.4@3950,2065 3950,2075 3890.63,2134.37 3890.63,2142.66 3894.53,2146.56 3894.53,2183.44 3865,2212.97 3865,2485 3945.47,2565.47 3945.47,2680.47 4235,2970 4235,3310 v1(4402.5,3477.5) ; v1(4685,3675) 5120,3675 U1.87@5170,3725
10.5: P9.1 U1.88 | length 2282.5
  Bottom Layer w10: U1.88@5170,3825 5172.5,3827.5 5172.5,4317.5 5180,4325 6520,4325 P9.1@6830,4015
  other v1: 5175,4320
10.6: P9.3 U1.89 | length 2763.3
  Bottom Layer w10: U1.89@5070,3725 5070,3774.61 5075.86,3780.47 5088.44,3780.47 5114.53,3806.56 5114.53,3843.44 5088.44,3869.53 5075.86,3869.53 5070,3875.39 v1(5070,4360) 6547.97,4360 6874.53,4033.44 6874.53,3959.53 P9.3@6830,3915
11.2: R44.2 U1.78 | length 1933.9
  Top Layer w10: v1(6507.74,2741.94) 6507.74,2731.12 6525.47,2713.38 6525.47,2706.56 6551.95,2680.08 6577.9,2680.08 6624.85,2633.12 6624.85,2607.18 6661.25,2570.78 6687.19,2570.78 6722.97,2535 R44.2@6783.5,2535
  Bottom Layer w10: U1.78@5670,3825 5625.47,3780.47 5625.47,3706.56 5651.56,3680.47 5787.96,3680.47 6505,2963.43 6505,2744.68 v1(6507.74,2741.94)
11.3: R45.2 U1.79 | length 1959.8
  Top Layer w10: v1@6460,2685 v1(6467.74,2685) 6475.47,2685 6525.47,2635 6525.47,2606.56 6561.07,2570.96 6587.01,2570.96 6622.6,2535.37 6622.6,2509.43 6656.76,2475.27 6682.7,2475.27 6724.93,2433.04 6724.93,2389.4 6761.42,2352.91 6777.65,2352.91 6783.5,2347.06 R45.2@6783.5,2320
  Bottom Layer w10: U1.79@5570,3725 6467.74,2827.26 v1(6467.74,2685)
11.6: P9.8 U1.80 | length 1733.2
  Top Layer w10: v1(5560,3565) 5567.65,3557.35 5583.51,3557.35 5585.86,3555 6226.57,3555 6241.1,3569.53 6784.53,3569.53 P9.8@6930,3715
  Bottom Layer w10: v1(5560,3565) 5525.47,3599.53 5525.47,3780.47 U1.80@5570,3825
11.9: P3.1 U1.81 | length 862
  Top Layer w10: P3.1@4820,3985 4938.38,3866.62 ccw(c4945.43,3873.71) 4940.86,3864.81 4940.92,3864.79 ccw(c4945.46,3873.69) 4949.91,3864.74 ; 4949.95,3864.76 cw(c4970,3825) 4999.69,3858.19 ccw(c5006.31,3865.68) 5006.27,3855.68 5033.73,3855.68 ccw(c5033.69,3865.68) 5040.32,3858.2 cw(c5070,3825) 5099.69,3858.19 ccw(c5106.31,3865.68) 5106.27,3855.68 5133.73,3855.68 ccw(c5133.69,3865.68) 5140.32,3858.2 cw(c5170,3825) 5199.69,3858.19 ccw(c5206.31,3865.68) 5206.27,3855.68 5216.68,3855.68 5219.61,3855.68 5225.47,3849.82 5225.47,3795.61 5246.08,3775 5282.97,3775 5316.11,3741.86 5316.11,3705.35 5340.98,3680.47 5425.47,3680.47 U1.81@5470,3725
11.10: P3.3 U1.82 | length 681.3
  Top Layer w10: P3.3@4920,3985 4964.53,4029.53 5260.47,4029.53 5275.47,4014.53 5275.47,3966.56 5301.56,3940.47 5354.53,3940.47 U1.82@5470,3825
11.11: P3.5 U1.83 | length 494.6
  Top Layer w10: P3.5@5020,3985 5027.5,3977.5 5064.53,3977.5 5102.03,3940 5165,3940 5235.47,3869.53 5288.44,3869.53 5320,3837.97 5320,3775 U1.83@5370,3725
11.12: P3.7 U1.84 | length 323.6
  Top Layer w10: P3.7@5120,3985 5169.61,3985 5175.47,3979.14 5175.47,3966.56 5201.56,3940.47 5244.96,3940.47 5295.91,3889.53 5296.73,3889.53 5361.26,3825 U1.84@5370,3825
13.0: P3.9 U1.74 | length 1025.1
  Top Layer w10: P3.9@5220,3985 5228.72,3985 5300.58,3913.14 5300.64,3913.14 5300.91,3912.87 5348.78,3871.93 5351.59,3869.53 5355.28,3869.53 5388.44,3869.53 5414.53,3843.44 5414.53,3790.47 5430,3775 5482.97,3775 5514.53,3743.44 5514.53,3706.56 5502.54,3694.57 5502.54,3694.28 5498.01,3689.76 5497.73,3689.76 5497.73,3685.63 5497.73,3660.86 5503.59,3655 5813.76,3655 5819.61,3660.86 5819.61,3774.61 U1.74@5870,3825
13.1: P3.11 U1.75 | length 834.2
  Top Layer w10: P3.11@5320,3985 5327.5,3977.5 5364.53,3977.5 5462.37,3879.66 5678.31,3879.66 5714.53,3843.44 5714.53,3775.39 5708.67,3769.53 5651.56,3769.53 5625.47,3743.44 5625.47,3706.56 5651.56,3680.47 5725.47,3680.47 U1.75@5770,3725
13.2: P3.13 U1.76 | length 416.3
  Top Layer w10: P3.13@5420,3985 5498.87,3906.13 5688.87,3906.13 U1.76@5770,3825
13.3: P3.15 U1.77 | length 568.4
  Top Layer w10: P3.15@5520,3985 5578.87,3926.13 5697.15,3926.13 5753.76,3869.53 5788.44,3869.53 5814.53,3843.44 5814.53,3806.56 5788.44,3780.47 5762.5,3780.47 5714.53,3732.5 5677.5,3732.5 U1.77@5670,3725
15.0: P3.12 U1.58 | length 1509.8
  Top Layer w10: P3.12@5320,4085 5327.5,4092.5 5364.53,4092.5 5401.56,4129.53 6313.44,4129.53 6345,4097.97 6345,4072.03 6377.03,4040 6455,4040 U1.58@6670,3825
15.1: P3.10 U1.59 | length 1613.1
  Top Layer w10: P3.10@5220,4085 5227.5,4077.5 5264.53,4077.5 5312.5,4029.53 5602.65,4029.53 5685.69,3946.49 6148.51,3946.49 6225,3870 6225,3807.03 6251.56,3780.47 6319.14,3780.47 6325,3774.61 6325,3739.05 6324.71,3738.76 6324.71,3707.32 6351.96,3680.07 6384.29,3680.07 6384.7,3680.47 6525.47,3680.47 U1.59@6570,3725
15.2: P3.14 U1.60 | length 1870.5
  Top Layer w10: v1(6500.78,3909.22) 6500.78,3901.72 6570,3832.5 U1.60@6570,3825
  Bottom Layer w10: P3.14@5420,4085 5420,4269.14 5425.86,4275 6461.57,4275 6660,4076.57 6660,4043.43 6597.11,3980.54 6570.54,3980.54 6500.78,3910.78 v1(6500.78,3909.22)
15.3: P3.6 U1.61 | length 2369.6
  Top Layer w10: P3.6@5020,4085 5104.53,4169.53 6401.73,4169.53 6681.73,3889.53 6696.73,3889.53 6734.53,3851.73 6734.53,3798.27 6714.53,3778.27 6714.53,3706.56 6688.44,3680.47 6648.6,3680.47 6620,3709.07 6620,3737.97 6588.44,3769.53 6551.56,3769.53 6525.47,3743.44 6525.47,3730.86 6519.61,3725 U1.61@6470,3725
15.4: P3.16 U1.62 | length 1057.7
  Top Layer w10: P3.16@5520,4085 5575.46,4085 5693.97,3966.49 6328.51,3966.49 U1.62@6470,3825
15.5: P3.8 U1.63 | length 2482.3
  Top Layer w10: P3.8@5120,4085 5127.5,4092.5 5164.53,4092.5 5221.56,4149.53 6393.44,4149.53 6673.44,3869.53 6688.44,3869.53 6714.53,3843.44 6714.53,3806.56 6688.44,3780.47 6651.56,3780.47 6625.47,3806.56 6625.47,3841.24 6517.5,3949.22 6484.22,3949.22 6456.64,3921.64 6456.64,3896.79 6484.22,3869.22 6500.78,3869.22 6514.53,3855.47 6514.53,3806.56 6488.44,3780.47 6425.47,3780.47 U1.63@6370,3725
15.6: P16.4 U1.64 | length 5513.7
  Top Layer w10: P16.4@4570,2080 4570,2137.44 4575.86,2143.3 4808.67,2143.3 4814.53,2137.44 4814.53,2040.86 4820.39,2035 5034.14,2035 5040,2029.14 v1(5040,1950) ; v1(5930,1955) 6009.53,1875.47 6993.76,1875.47 7090,1971.72 7090,3785 v1(7025,3850)
  Bottom Layer w10: v1(5040,1950) 5925,1950 v1(5930,1955) ; U1.64@6370,3825 6414.53,3869.53 6483.9,3869.53 6484.22,3869.22 6551.24,3869.22 6551.56,3869.53 6688.44,3869.53 6787.5,3770.47 6848.44,3770.47 6880,3802.03 6880,3827.97 6911.56,3859.53 6967.61,3859.53 6972.61,3854.53 7020.47,3854.53 v1(7025,3850)
15.7: P16.3 U1.65 | length 5477.3
  Top Layer w10: P16.3@4670,2080 4725,2025 4725,1870.86 4730.86,1865 4979.14,1865 4985,1870.86 v1(4985,1995) ; v1(5995,2000) 6048.74,2000 6153.27,1895.47 6985.47,1895.47 7070,1980 7070,3736.97 v1(7031.62,3775.35)
  Bottom Layer w10: v1(4985,1995) 5990,1995 v1(5995,2000) ; U1.65@6270,3725 6314.53,3769.53 6688.44,3769.53 6787.5,3670.47 6848.44,3670.47 6880.77,3702.8 6880.77,3728.74 6920.76,3768.73 7025,3768.73 v1(7031.62,3775.35)
15.8: P10.6 U1.66 | length 3669.4
  Top Layer w10: v1(6620,4060) 6620,4139.14 6625.86,4145 6875,4145 v1(6880,4140)
  Bottom Layer w10: U1.66@6270,3825 6270,3838.27 6283.99,3852.26 6283.99,3853.99 6490,4060 v1(6620,4060) ; P10.6@6360,1980 6360,1974.6 6429.13,1905.47 6707.04,1905.47 7071.62,2270.05 7071.62,3988.75 6925,4135.37 6884.63,4135.37 v1(6880,4140)
20.0: P14.3 U1.44 | length 3721.8
  Top Layer w10: v1(6678.05,1975.47) 6681,1972.52 6887.29,1972.52 v1(6890.25,1969.57)
  Bottom Layer w10: P14.3@4353.03,2165 4400,2118.03 4400,1905 4459.53,1845.47 6766.15,1845.47 v1(6890.25,1969.57) ; U1.44@6570,2525 6577.5,2517.5 6614.53,2517.5 6652.5,2479.53 6678.44,2479.53 6714.53,2443.44 6714.53,2206.56 6678.05,2170.07 v1(6678.05,1975.47)
20.3: P14.4 U1.46 | length 3807.7
  Top Layer w10: v1(6746.29,2043.71) 6753.94,2036.06 6785.23,2036.06 6791.29,2030 6944.14,2030 6950,2024.14 v1(6950,1975)
  Bottom Layer w10: P14.4@4353.03,2065 4353.03,1923.68 4451.24,1825.47 6825.47,1825.47 6944.22,1944.22 6944.22,1969.22 v1(6950,1975) ; U1.46@6570,2625 6625.47,2569.53 6688.44,2569.53 6746.29,2511.68 v1(6746.29,2043.71)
